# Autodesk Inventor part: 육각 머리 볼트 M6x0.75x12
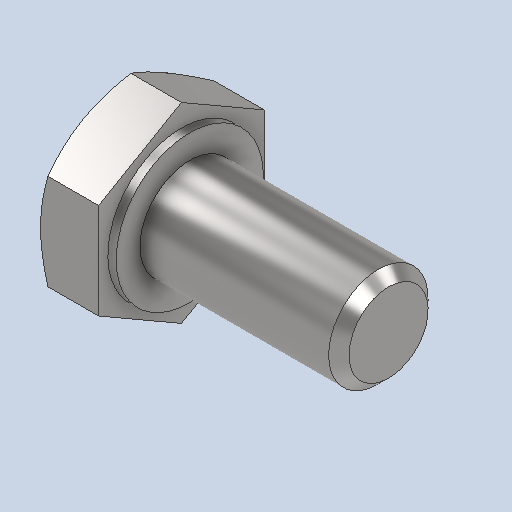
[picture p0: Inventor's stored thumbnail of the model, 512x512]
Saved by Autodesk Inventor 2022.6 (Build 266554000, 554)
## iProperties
Created: 2024-09
Part Number: 육각 머리 볼트 M6x0.75x12
Material: 강철, 연강
Description: 6각 머리 볼트 및 6각 머리 나사
Document SubType Name: Modeling
Designer: Class 001
Density: 7.85 g/cm^3
Appearance: 기본값
Author: jhkim
Sending System: Autodesk Inventor 2025
Preprocessor: ST-DEVELOPER v20
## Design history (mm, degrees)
feature "Solid1"
node "솔리드1"
